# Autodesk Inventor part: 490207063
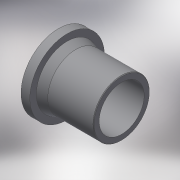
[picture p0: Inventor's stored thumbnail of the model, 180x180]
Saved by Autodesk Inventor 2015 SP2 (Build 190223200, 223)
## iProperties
Created: 2017-07
Part Number: 490207063
Material: Generic
Description: Stub Flange 63
Document SubType Name: Modeling
Designer: Кирилл
Mass: 216.918 g
Surface Area: 567.362 cm^2
Volume: 216.918 cm^3
Density: 1 g/cm^3
Appearance: Default
Author: Кирилл
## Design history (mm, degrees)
derived "490207.ipt"
feature "Solid1::490207.ipt"
tag "TaggingFeature1"
body "Solid1"
other parameters: "d1" = 75, "d2" = 63, "d3" = 50.4, "d4" = 102, "d5" = 14, "d6" = 87, "d16" = 63, "d17" = 1.26, "d18" = 1.26, "d19" = 1.26, "d21" = 1.26, "d24" = 1.26, "d25" = 1.26, "d26" = 0.63, "d27" = 0, "d32" = 0.63, "d_" = 63, "L_1" = 87, "D_" = 102, "D_1" = 75, "a_" = 14
